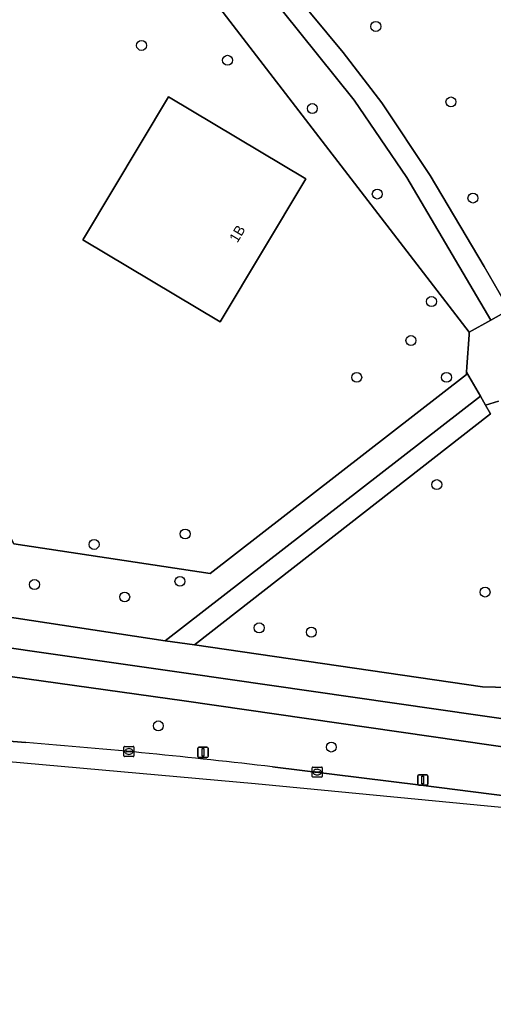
# Model space of a CAD drawing. Extents: x 162722 to 165104, y 384719 to 386284.
# Drawn here: x 163041.9 to 163088.5, y 385385.9 to 385481.8 of the extents above; entities that cross this region are included whole.
import ezdxf

# ---------------------------------------------------------------- set-up
doc = ezdxf.new("R2010")
doc.units = 0
for name, color, linetype in [('IMGEO_Berm_groen', 7, 'Continuous'), ('IMGEO_Boom', 7, 'Continuous'), ('IMGEO_Erf', 7, 'Continuous'), ('IMGEO_Fietspad_gesloten', 7, 'Continuous'), ('IMGEO_Groenvoorziening', 7, 'Continuous'), ('IMGEO_Kolk', 7, 'Continuous'), ('IMGEO_Lichtmast', 7, 'Continuous'), ('IMGEO_Loofbos', 7, 'Continuous'), ('IMGEO_Pand', 7, 'Continuous'), ('IMGEO_Pand_nummerreeks', 7, 'Continuous'), ('IMGEO_Rijbaan_lokaal_gesloten', 7, 'Continuous'), ('IMGEO_Rijbaan_lokaal_halfverhard', 7, 'Continuous'), ('IMGEO_Rijbaan_lokaal_open', 7, 'Continuous'), ('IMGEO_Voetpad_halfverhard', 7, 'Continuous'), ('IMGEO_Voetpad_open', 7, 'Continuous')]:
    doc.layers.add(name, color=color, linetype=linetype)

msp = doc.modelspace()

# ---------------------------------------------------------------- linework, layer by layer
at = {"layer": 'IMGEO_Berm_groen'}
for points in [[(163058.121, 385414.782), (163022.454, 385419.756), (163017.074, 385420.501)], [(163109.638, 385407.325), (163058.121, 385414.782)], [(163004.018, 385413.781), (163013.498, 385412.976), (163042.535, 385410.67)], [(163066.81, 385408.27), (163081.394, 385406.487), (163093.48, 385404.933)]]:
    msp.add_lwpolyline(points, dxfattribs=at)
msp.add_arc((162991.359, 384769.082), 643.626, 83.267863, 85.439495, dxfattribs=at)
at = {"layer": 'IMGEO_Boom'}
for centre in [(163076.967, 385481.093), (163053.921, 385479.228), (163062.38, 385477.766), (163084.355, 385473.671), (163070.72, 385473.019), (163077.109, 385464.612), (163086.519, 385464.214), (163082.44, 385454.038), (163080.422, 385450.202), (163075.088, 385446.582), (163083.915, 385446.582), (163082.964, 385436.031), (163058.213, 385431.175), (163049.259, 385430.147), (163043.397, 385426.201), (163057.702, 385426.517), (163052.267, 385424.981), (163087.711, 385425.463), (163065.493, 385421.938), (163070.621, 385421.52), (163055.574, 385412.305), (163072.588, 385410.217)]:
    msp.add_circle(centre, 0.489, dxfattribs=at)
at = {"layer": 'IMGEO_Erf'}
for points in [[(163048.49, 385500), (163046.824, 385502.152), (163043.877, 385500), (163015.707, 385479.424), (163041.362, 385430.205), (163060.661, 385427.284), (163085.872, 385446.874), (163085.887, 385447.091), (163085.923, 385447.617), (163086.141, 385450.768), (163086.158, 385451.027)], [(163061.669, 385452.033), (163048.161, 385460.109), (163048.314, 385460.365), (163056.576, 385474.185), (163070.085, 385466.109)]]:
    msp.add_lwpolyline(points, close=True, dxfattribs=at)
at = {"layer": 'IMGEO_Fietspad_gesloten'}
for points in [[(163110.177, 385409.999), (163095.179, 385412.164), (163058.54, 385417.454), (163026.168, 385422.069)], [(163017.074, 385420.501), (163022.454, 385419.756), (163058.121, 385414.782), (163109.638, 385407.325)]]:
    msp.add_lwpolyline(points, dxfattribs=at)
at = {"layer": 'IMGEO_Groenvoorziening'}
for points in [[(163043.877, 385500), (163046.824, 385502.152), (163048.49, 385500), (163086.158, 385451.027), (163088.288, 385452.21), (163080.016, 385466.238), (163074.845, 385473.83), (163053.861, 385500), (163052.046, 385502.264), (163046.585, 385508.238), (163039.88, 385512.477), (163026.036, 385519.986), (163018.62, 385523.736), (163011.2, 385526.708), (163003.668, 385528.819), (163000, 385529.535), (162963.672, 385536.629), (162948.475, 385539.895), (162925.687, 385545.884), (162916.215, 385547.954)], [(163015.718, 385426.626), (163018.644, 385426.352), (163024.306, 385425.516), (163056.246, 385420.663), (163087.262, 385444.719), (163085.887, 385447.091), (163085.872, 385446.874), (163060.661, 385427.284), (163041.362, 385430.205), (163015.707, 385479.424), (163043.877, 385500)]]:
    msp.add_lwpolyline(points, dxfattribs=at)
at = {"layer": 'IMGEO_Kolk'}
for p, q in [((163052.179, 385409.357), (163052.179, 385410.209)), ((163052.254, 385410.283), (163053.106, 385410.283)), ((163052.438, 385409.777), (163052.438, 385409.789)), ((163052.481, 385409.826), (163052.879, 385409.826)), ((163052.667, 385410.063), (163052.692, 385410.063)), ((163052.922, 385409.789), (163052.922, 385409.777)), ((163053.18, 385410.209), (163053.18, 385409.357)), ((163053.106, 385409.283), (163052.254, 385409.283)), ((163052.876, 385409.74), (163052.478, 385409.74)), ((163052.69, 385409.503), (163052.665, 385409.503)), ((163070.7, 385407.328), (163070.7, 385408.18)), ((163070.775, 385408.254), (163071.627, 385408.254)), ((163071.188, 385408.034), (163071.213, 385408.034)), ((163071.701, 385408.18), (163071.701, 385407.328)), ((163071.627, 385407.254), (163070.775, 385407.254)), ((163070.959, 385407.748), (163070.959, 385407.76)), ((163071.397, 385407.711), (163070.999, 385407.711)), ((163071.002, 385407.797), (163071.4, 385407.797)), ((163071.211, 385407.474), (163071.186, 385407.474)), ((163071.443, 385407.76), (163071.443, 385407.748))]:
    msp.add_line(p, q, dxfattribs=at)
for points in [[(163052.179, 385409.357), (163052.179, 385410.209)], [(163052.254, 385410.283), (163053.106, 385410.283)], [(163053.18, 385410.209), (163053.18, 385409.357)], [(163053.106, 385409.283), (163052.254, 385409.283)], [(163070.7, 385407.328), (163070.7, 385408.18)], [(163070.775, 385408.254), (163071.627, 385408.254)], [(163071.701, 385408.18), (163071.701, 385407.328)], [(163071.627, 385407.254), (163070.775, 385407.254)]]:
    msp.add_lwpolyline(points, dxfattribs=at)
for centre, radius, start, end in [((163052.256, 385410.207), 0.0765, 91.55205, 178.44795), ((163052.256, 385410.207), 0.0765, 91.55205, 178.44795), ((163052.478, 385409.786), 0.0403, 85.87752, 175.75265), ((163052.475, 385409.776), 0.0366, 178.93798, 274.71019), ((163052.879, 385409.783), 0.043, 264.86636, 352.45326), ((163052.883, 385409.788), 0.0386, 1.73085, 96.63898), ((163053.104, 385410.207), 0.0765, 1.55205, 88.44795), ((163053.104, 385410.207), 0.0765, 1.55205, 88.44795), ((163052.256, 385409.359), 0.0765, 181.55205, 268.44795), ((163052.256, 385409.359), 0.0765, 181.55205, 268.44795), ((163053.104, 385409.359), 0.0765, 271.55205, 358.44795), ((163053.104, 385409.359), 0.0765, 271.55205, 358.44795), ((163070.777, 385408.178), 0.0765, 91.55205, 178.44795), ((163070.777, 385408.178), 0.0765, 91.55205, 178.44795), ((163071.625, 385408.178), 0.0765, 1.55205, 88.44795), ((163071.625, 385408.178), 0.0765, 1.55205, 88.44795), ((163070.777, 385407.33), 0.0765, 181.55205, 268.44795), ((163070.777, 385407.33), 0.0765, 181.55205, 268.44795), ((163070.999, 385407.757), 0.0403, 85.87752, 175.75265), ((163070.996, 385407.747), 0.0366, 178.93798, 274.71019), ((163071.4, 385407.754), 0.043, 264.86636, 352.45326), ((163071.404, 385407.759), 0.0386, 1.73085, 96.63898), ((163071.625, 385407.33), 0.0765, 271.55205, 358.44795), ((163071.625, 385407.33), 0.0765, 271.55205, 358.44795)]:
    msp.add_arc(centre, radius, start, end, dxfattribs=at)
for centre, major_axis, ratio, start_param, end_param in [((163052.666, 385409.783), (-0.387, 0.002), 0.722429, 4.712389, 7.853982), ((163052.691, 385409.783), (-0.39, 0.002), 0.717154, 1.570796, 4.712389), ((163071.187, 385407.754), (-0.387, 0.002), 0.722429, 4.712389, 7.853982), ((163071.212, 385407.754), (-0.39, 0.002), 0.717154, 1.570796, 4.712389)]:
    msp.add_ellipse(centre, major_axis=major_axis, ratio=ratio, start_param=start_param, end_param=end_param, dxfattribs=at)
at = {"layer": 'IMGEO_Lichtmast'}
for p, q in [((163059.47, 385409.3), (163059.47, 385410.1)), ((163059.47, 385410.1), (163059.47, 385409.3)), ((163059.57, 385410.2), (163060.36, 385410.2)), ((163060.36, 385410.2), (163059.57, 385410.2)), ((163060.46, 385410.1), (163060.46, 385409.3)), ((163060.46, 385409.3), (163060.46, 385410.1)), ((163060.36, 385409.2), (163059.57, 385409.2)), ((163059.57, 385409.2), (163060.36, 385409.2)), ((163081.084, 385406.585), (163081.084, 385407.385)), ((163081.084, 385407.385), (163081.084, 385406.585)), ((163081.184, 385407.485), (163081.974, 385407.485)), ((163081.974, 385407.485), (163081.184, 385407.485)), ((163082.074, 385407.385), (163082.074, 385406.585)), ((163082.074, 385406.585), (163082.074, 385407.385)), ((163081.974, 385406.485), (163081.184, 385406.485)), ((163081.184, 385406.485), (163081.974, 385406.485))]:
    msp.add_line(p, q, dxfattribs=at)
for points in [[(163059.89, 385410.075), (163060.04, 385410.075), (163060.04, 385409.325), (163059.89, 385409.325), (163059.89, 385410.075)], [(163081.504, 385407.36), (163081.654, 385407.36), (163081.654, 385406.61), (163081.504, 385406.61), (163081.504, 385407.36)]]:
    msp.add_lwpolyline(points, dxfattribs=at)
for centre, start, end in [((163059.57, 385410.1), 90, 180), ((163059.57, 385410.1), 90, 180), ((163060.36, 385410.1), 0, 90), ((163060.36, 385410.1), 360, 90), ((163059.57, 385409.3), 180, 270), ((163059.57, 385409.3), 180, 270), ((163060.36, 385409.3), 270, 0), ((163060.36, 385409.3), 270, 0), ((163081.184, 385407.385), 90, 180), ((163081.184, 385407.385), 90, 180), ((163081.974, 385407.385), 0, 90), ((163081.974, 385407.385), 360, 90), ((163081.184, 385406.585), 180, 270), ((163081.184, 385406.585), 180, 270), ((163081.974, 385406.585), 270, 0), ((163081.974, 385406.585), 270, 0)]:
    msp.add_arc(centre, 0.1, start, end, dxfattribs=at)
at = {"layer": 'IMGEO_Loofbos'}
for points in [[(163063.945, 385490.383), (163073.768, 385478.525), (163077.565, 385473.594), (163082.315, 385466.43), (163087.634, 385457.479), (163090.079, 385453.228), (163091.761, 385450.255), (163107.063, 385458.212), (163104.137, 385462.871), (163099.792, 385469.938), (163094.495, 385476.185), (163089.045, 385484.615)], [(163089.043, 385444.237), (163087.758, 385443.862), (163088.258, 385442.999), (163059.128, 385420.258), (163087.455, 385416.144), (163091.285, 385416.054), (163094.793, 385416.322), (163099.175, 385417.23), (163100.488, 385417.453)]]:
    msp.add_lwpolyline(points, dxfattribs=at)
at = {"layer": 'IMGEO_Pand'}
msp.add_lwpolyline([(163048.314, 385460.365), (163048.161, 385460.109), (163061.669, 385452.033), (163070.085, 385466.109), (163056.576, 385474.185)], close=True, dxfattribs=at)
at = {"layer": 'IMGEO_Rijbaan_lokaal_gesloten'}
for points in [[(163042.535, 385410.67), (163013.498, 385412.976), (163004.018, 385413.781), (163000.639, 385414.049), (162996.33, 385414.384), (162996.163, 385412.347), (162996.163, 385412.347), (163006.365, 385411.869), (163065.084, 385406.643), (163092.741, 385403.99), (163118.125, 385400.011), (163166.998, 385386.746), (163178.834, 385382.11), (163197.766, 385374.695), (163266.908, 385342.671), (163292.671, 385328.838), (163310.131, 385318.231)], [(163093.48, 385404.933), (163081.394, 385406.487), (163066.81, 385408.27)]]:
    msp.add_lwpolyline(points, dxfattribs=at)
msp.add_arc((162991.359, 384769.082), 643.626, 83.267863, 85.439495, dxfattribs=at)
at = {"layer": 'IMGEO_Rijbaan_lokaal_halfverhard'}
msp.add_lwpolyline([(163053.861, 385500), (163074.845, 385473.83), (163080.016, 385466.238), (163088.288, 385452.21), (163090.079, 385453.228), (163087.634, 385457.479), (163082.315, 385466.43), (163077.565, 385473.594), (163073.768, 385478.525), (163063.945, 385490.383)], dxfattribs=at)
at = {"layer": 'IMGEO_Rijbaan_lokaal_open'}
msp.add_lwpolyline([(163091.761, 385450.255), (163090.079, 385453.228), (163088.288, 385452.21), (163086.158, 385451.027), (163086.141, 385450.768), (163085.923, 385447.617), (163085.887, 385447.091), (163087.262, 385444.719), (163087.758, 385443.862), (163089.043, 385444.237)], dxfattribs=at)
at = {"layer": 'IMGEO_Voetpad_halfverhard'}
msp.add_lwpolyline([(163087.758, 385443.862), (163087.262, 385444.719), (163056.246, 385420.663), (163059.128, 385420.258), (163088.258, 385442.999)], close=True, dxfattribs=at)
at = {"layer": 'IMGEO_Voetpad_open'}
for points in [[(163137.683, 385414.47), (163137.068, 385414.788), (163127.787, 385418.663), (163123.979, 385418.859), (163117.089, 385418.91), (163110.388, 385418.552), (163108.21, 385418.448), (163100.488, 385417.453), (163099.175, 385417.23), (163094.793, 385416.322), (163091.285, 385416.054), (163087.455, 385416.144), (163059.128, 385420.258), (163056.246, 385420.663), (163024.306, 385425.516)], [(163017.969, 385423.237), (163026.168, 385422.069), (163058.54, 385417.454), (163095.179, 385412.164), (163095.381, 385413.513)]]:
    msp.add_lwpolyline(points, dxfattribs=at)

# ---------------------------------------------------------------- texts
at = {"layer": 'IMGEO_Pand_nummerreeks'}
msp.add_text('1B', height=1, rotation=59.12658, dxfattribs=at).set_placement((163063.348, 385459.752))

doc.saveas('drawing.dxf')
